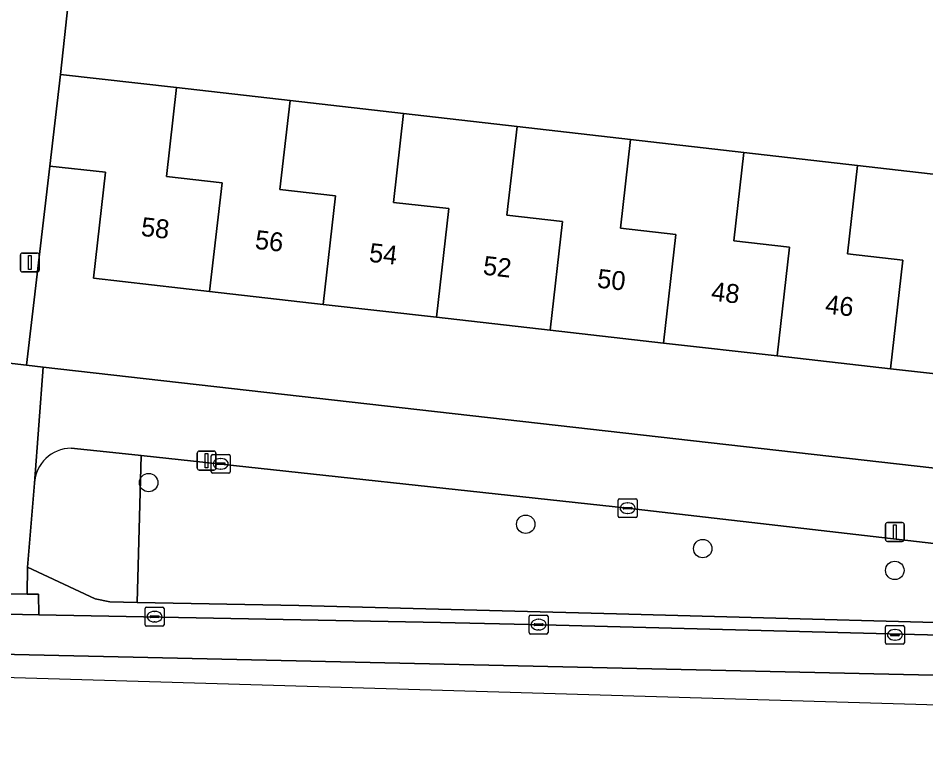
# Model space of a CAD drawing. Extents: x 162082 to 163401, y 388089 to 388636.
# Drawn here: x 162750.85 to 162798.94, y 388092.06 to 388131.14 of the extents above; entities that cross this region are included whole.
import ezdxf

# ---------------------------------------------------------------- set-up
doc = ezdxf.new("R2010")
doc.units = 0
for name, color, linetype in [('IMGEO_Boom', 7, 'Continuous'), ('IMGEO_Erf', 7, 'Continuous'), ('IMGEO_Groenvoorziening', 7, 'Continuous'), ('IMGEO_Kolk', 7, 'Continuous'), ('IMGEO_Lichtmast', 7, 'Continuous'), ('IMGEO_Pand', 7, 'Continuous'), ('IMGEO_Pand_nummerreeks', 7, 'Continuous'), ('IMGEO_Parkeervlak_gesloten', 7, 'Continuous'), ('IMGEO_Rijbaan_lokaal_gesloten', 7, 'Continuous'), ('IMGEO_Voetpad_open', 7, 'Continuous')]:
    doc.layers.add(name, color=color, linetype=linetype)

msp = doc.modelspace()

# ---------------------------------------------------------------- linework, layer by layer
at = {"layer": 'IMGEO_Boom'}
for centre in [(162757.767, 388106.537), (162777.745, 388104.33), (162787.124, 388103.04), (162797.299, 388101.885)]:
    msp.add_circle(centre, 0.489, dxfattribs=at)
at = {"layer": 'IMGEO_Erf'}
for points in [[(162817.616, 388132.026), (162813.209, 388132.465), (162813.117, 388131.452), (162774.618, 388135.355), (162754.126, 388137.65), (162753.09, 388128.162), (162759.25, 388127.458), (162765.261, 388126.772), (162771.273, 388126.085), (162777.284, 388125.399), (162783.297, 388124.712), (162789.309, 388124.025), (162795.321, 388123.339), (162801.333, 388122.652), (162807.344, 388121.965), (162813.503, 388121.262), (162816.444, 388120.926)], [(162797.073, 388112.567), (162791.061, 388113.249), (162785.049, 388113.931), (162779.036, 388114.613), (162773.023, 388115.295), (162767.011, 388115.977), (162760.999, 388116.659), (162754.84, 388117.358), (162755.477, 388122.974), (162752.539, 388123.307), (162751.303, 388112.757), (162752.175, 388112.658), (162814.697, 388105.571), (162815.061, 388108.754), (162815.261, 388110.504), (162809.099, 388111.203), (162803.086, 388111.885)]]:
    msp.add_lwpolyline(points, close=True, dxfattribs=at)
at = {"layer": 'IMGEO_Groenvoorziening'}
msp.add_lwpolyline([(162751.719, 388106.5), (162751.357, 388102.059), (162754.926, 388100.382), (162755.718, 388100.214), (162757.157, 388100.187), (162757.371, 388107.966), (162755.871, 388108.128), (162753.663, 388108.356)], dxfattribs=at)
msp.add_lwpolyline([(162765.73, 388100.028), (162782.561, 388099.591), (162807.227, 388098.913), (162807.323, 388102.396), (162783.141, 388105.183), (162757.371, 388107.966), (162757.157, 388100.187)], close=True, dxfattribs=at)
msp.add_arc((162753.669, 388106.404), 1.952, 90.1741, 177.1727, dxfattribs=at)
at = {"layer": 'IMGEO_Kolk'}
for p, q in [((162761.085, 388107.106), (162761.085, 388107.958)), ((162761.16, 388108.032), (162762.012, 388108.032)), ((162761.573, 388107.812), (162761.598, 388107.812)), ((162762.086, 388107.958), (162762.086, 388107.106)), ((162761.344, 388107.526), (162761.344, 388107.538)), ((162761.782, 388107.489), (162761.384, 388107.489)), ((162761.387, 388107.575), (162761.785, 388107.575)), ((162761.596, 388107.252), (162761.571, 388107.252)), ((162761.828, 388107.538), (162761.828, 388107.526)), ((162762.012, 388107.032), (162761.16, 388107.032)), ((162782.719, 388105.683), (162783.571, 388105.683)), ((162782.644, 388104.757), (162782.644, 388105.609)), ((162782.946, 388105.226), (162783.344, 388105.226)), ((162783.132, 388105.463), (162783.157, 388105.463)), ((162783.645, 388105.609), (162783.645, 388104.757)), ((162782.903, 388105.177), (162782.903, 388105.189)), ((162783.341, 388105.14), (162782.943, 388105.14)), ((162783.155, 388104.903), (162783.13, 388104.903)), ((162783.387, 388105.189), (162783.387, 388105.177)), ((162783.571, 388104.683), (162782.719, 388104.683)), ((162757.657, 388099.935), (162758.509, 388099.935)), ((162757.582, 388099.009), (162757.582, 388099.861)), ((162757.841, 388099.429), (162757.841, 388099.441)), ((162757.884, 388099.478), (162758.282, 388099.478)), ((162758.07, 388099.715), (162758.095, 388099.715)), ((162758.325, 388099.441), (162758.325, 388099.429)), ((162758.583, 388099.861), (162758.583, 388099.009)), ((162777.926, 388098.589), (162777.926, 388099.441)), ((162778.001, 388099.515), (162778.853, 388099.515)), ((162778.927, 388099.441), (162778.927, 388098.589)), ((162758.279, 388099.392), (162757.881, 388099.392)), ((162758.093, 388099.155), (162758.068, 388099.155)), ((162778.185, 388099.009), (162778.185, 388099.021)), ((162778.623, 388098.972), (162778.225, 388098.972)), ((162778.228, 388099.058), (162778.626, 388099.058)), ((162778.414, 388099.295), (162778.439, 388099.295)), ((162778.669, 388099.021), (162778.669, 388099.009)), ((162796.881, 388098.97), (162797.733, 388098.97)), ((162758.509, 388098.935), (162757.657, 388098.935)), ((162778.853, 388098.515), (162778.001, 388098.515)), ((162778.437, 388098.735), (162778.412, 388098.735)), ((162796.806, 388098.044), (162796.806, 388098.896)), ((162797.065, 388098.464), (162797.065, 388098.476)), ((162797.108, 388098.513), (162797.506, 388098.513)), ((162797.294, 388098.75), (162797.319, 388098.75)), ((162797.549, 388098.476), (162797.549, 388098.464)), ((162797.807, 388098.896), (162797.807, 388098.044)), ((162797.503, 388098.427), (162797.105, 388098.427)), ((162797.317, 388098.19), (162797.292, 388098.19)), ((162797.733, 388097.97), (162796.881, 388097.97))]:
    msp.add_line(p, q, dxfattribs=at)
for points in [[(162761.085, 388107.106), (162761.085, 388107.958)], [(162761.16, 388108.032), (162762.012, 388108.032)], [(162762.086, 388107.958), (162762.086, 388107.106)], [(162762.012, 388107.032), (162761.16, 388107.032)], [(162782.719, 388105.683), (162783.571, 388105.683)], [(162782.644, 388104.757), (162782.644, 388105.609)], [(162783.645, 388105.609), (162783.645, 388104.757)], [(162783.571, 388104.683), (162782.719, 388104.683)], [(162757.657, 388099.935), (162758.509, 388099.935)], [(162757.582, 388099.009), (162757.582, 388099.861)], [(162758.583, 388099.861), (162758.583, 388099.009)], [(162777.926, 388098.589), (162777.926, 388099.441)], [(162778.001, 388099.515), (162778.853, 388099.515)], [(162778.927, 388099.441), (162778.927, 388098.589)], [(162796.881, 388098.97), (162797.733, 388098.97)], [(162758.509, 388098.935), (162757.657, 388098.935)], [(162778.853, 388098.515), (162778.001, 388098.515)], [(162796.806, 388098.044), (162796.806, 388098.896)], [(162797.807, 388098.896), (162797.807, 388098.044)], [(162797.733, 388097.97), (162796.881, 388097.97)]]:
    msp.add_lwpolyline(points, dxfattribs=at)
for centre, radius, start, end in [((162761.162, 388107.956), 0.0765, 91.552, 178.448), ((162761.162, 388107.956), 0.0765, 91.552, 178.448), ((162762.01, 388107.956), 0.0765, 1.552, 88.448), ((162762.01, 388107.956), 0.0765, 1.552, 88.448), ((162761.384, 388107.535), 0.0403, 85.8775, 175.7526), ((162761.381, 388107.525), 0.0366, 178.938, 274.7102), ((162761.785, 388107.532), 0.043, 264.8664, 352.4533), ((162761.789, 388107.537), 0.0386, 1.7309, 96.639), ((162761.162, 388107.108), 0.0765, 181.552, 268.448), ((162761.162, 388107.108), 0.0765, 181.552, 268.448), ((162762.01, 388107.108), 0.0765, 271.552, 358.448), ((162762.01, 388107.108), 0.0765, 271.552, 358.448), ((162782.721, 388105.607), 0.0765, 91.552, 178.448), ((162782.721, 388105.607), 0.0765, 91.552, 178.448), ((162783.569, 388105.607), 0.0765, 1.552, 88.448), ((162783.569, 388105.607), 0.0765, 1.552, 88.448), ((162782.943, 388105.186), 0.0403, 85.8775, 175.7526), ((162783.348, 388105.188), 0.0386, 1.7309, 96.639), ((162782.721, 388104.759), 0.0765, 181.552, 268.448), ((162782.721, 388104.759), 0.0765, 181.552, 268.448), ((162782.94, 388105.176), 0.0366, 178.938, 274.7102), ((162783.344, 388105.183), 0.043, 264.8664, 352.4533), ((162783.569, 388104.759), 0.0765, 271.552, 358.448), ((162783.569, 388104.759), 0.0765, 271.552, 358.448), ((162757.659, 388099.859), 0.0765, 91.552, 178.448), ((162757.659, 388099.859), 0.0765, 91.552, 178.448), ((162758.507, 388099.859), 0.0765, 1.552, 88.448), ((162758.507, 388099.859), 0.0765, 1.552, 88.448), ((162757.881, 388099.438), 0.0403, 85.8775, 175.7526), ((162757.878, 388099.428), 0.0366, 178.938, 274.7102), ((162758.282, 388099.435), 0.043, 264.8664, 352.4533), ((162758.286, 388099.44), 0.0386, 1.7309, 96.639), ((162778.003, 388099.439), 0.0765, 91.552, 178.448), ((162778.003, 388099.439), 0.0765, 91.552, 178.448), ((162778.851, 388099.439), 0.0765, 1.552, 88.448), ((162778.851, 388099.439), 0.0765, 1.552, 88.448), ((162757.659, 388099.011), 0.0765, 181.552, 268.448), ((162757.659, 388099.011), 0.0765, 181.552, 268.448), ((162758.507, 388099.011), 0.0765, 271.552, 358.448), ((162758.507, 388099.011), 0.0765, 271.552, 358.448), ((162778.225, 388099.018), 0.0403, 85.8775, 175.7526), ((162778.222, 388099.008), 0.0366, 178.938, 274.7102), ((162778.626, 388099.015), 0.043, 264.8664, 352.4533), ((162778.63, 388099.02), 0.0386, 1.7309, 96.639), ((162796.883, 388098.894), 0.0765, 91.552, 178.448), ((162796.883, 388098.894), 0.0765, 91.552, 178.448), ((162797.731, 388098.894), 0.0765, 1.552, 88.448), ((162797.731, 388098.894), 0.0765, 1.552, 88.448), ((162778.003, 388098.591), 0.0765, 181.552, 268.448), ((162778.003, 388098.591), 0.0765, 181.552, 268.448), ((162778.851, 388098.591), 0.0765, 271.552, 358.448), ((162778.851, 388098.591), 0.0765, 271.552, 358.448), ((162797.105, 388098.473), 0.0403, 85.8775, 175.7526), ((162797.102, 388098.463), 0.0366, 178.938, 274.7102), ((162797.506, 388098.47), 0.043, 264.8664, 352.4533), ((162797.51, 388098.475), 0.0386, 1.7309, 96.639), ((162796.883, 388098.046), 0.0765, 181.552, 268.448), ((162796.883, 388098.046), 0.0765, 181.552, 268.448), ((162797.731, 388098.046), 0.0765, 271.552, 358.448), ((162797.731, 388098.046), 0.0765, 271.552, 358.448)]:
    msp.add_arc(centre, radius, start, end, dxfattribs=at)
for centre, major_axis, ratio, start_param, end_param in [((162761.572, 388107.532), (-0.387, 0.002), 0.722429, 4.712389, 7.853982), ((162761.597, 388107.532), (-0.39, 0.002), 0.717154, 1.570796, 4.712389), ((162783.131, 388105.183), (-0.387, 0.002), 0.722429, 4.712389, 7.853982), ((162783.156, 388105.183), (-0.39, 0.002), 0.717154, 1.570796, 4.712389), ((162758.069, 388099.435), (-0.387, 0.002), 0.722429, 4.712389, 7.853982), ((162758.094, 388099.435), (-0.39, 0.002), 0.717154, 1.570796, 4.712389), ((162778.413, 388099.015), (-0.387, 0.002), 0.722429, 4.712389, 7.853982), ((162778.438, 388099.015), (-0.39, 0.002), 0.717154, 1.570796, 4.712389), ((162797.293, 388098.47), (-0.387, 0.002), 0.722429, 4.712389, 7.853982), ((162797.318, 388098.47), (-0.39, 0.002), 0.717154, 1.570796, 4.712389)]:
    msp.add_ellipse(centre, major_axis=major_axis, ratio=ratio, start_param=start_param, end_param=end_param, dxfattribs=at)
at = {"layer": 'IMGEO_Lichtmast'}
for p, q in [((162751.077, 388118.698), (162751.867, 388118.698)), ((162751.867, 388118.698), (162751.077, 388118.698)), ((162750.977, 388117.798), (162750.977, 388118.598)), ((162750.977, 388118.598), (162750.977, 388117.798)), ((162751.967, 388118.598), (162751.967, 388117.798)), ((162751.967, 388117.798), (162751.967, 388118.598)), ((162751.867, 388117.698), (162751.077, 388117.698)), ((162751.077, 388117.698), (162751.867, 388117.698)), ((162760.339, 388107.302), (162760.339, 388108.102)), ((162760.339, 388108.102), (162760.339, 388107.302)), ((162760.439, 388108.202), (162761.229, 388108.202)), ((162761.229, 388108.202), (162760.439, 388108.202)), ((162761.329, 388108.102), (162761.329, 388107.302)), ((162761.329, 388107.302), (162761.329, 388108.102)), ((162761.229, 388107.202), (162760.439, 388107.202)), ((162760.439, 388107.202), (162761.229, 388107.202)), ((162796.805, 388103.52), (162796.805, 388104.32)), ((162796.805, 388104.32), (162796.805, 388103.52)), ((162796.905, 388104.42), (162797.695, 388104.42)), ((162797.695, 388104.42), (162796.905, 388104.42)), ((162797.795, 388104.32), (162797.795, 388103.52)), ((162797.795, 388103.52), (162797.795, 388104.32)), ((162797.695, 388103.42), (162796.905, 388103.42)), ((162796.905, 388103.42), (162797.695, 388103.42))]:
    msp.add_line(p, q, dxfattribs=at)
for points in [[(162751.397, 388118.573), (162751.547, 388118.573), (162751.547, 388117.823), (162751.397, 388117.823), (162751.397, 388118.573)], [(162760.759, 388108.077), (162760.909, 388108.077), (162760.909, 388107.327), (162760.759, 388107.327), (162760.759, 388108.077)], [(162797.225, 388104.295), (162797.375, 388104.295), (162797.375, 388103.545), (162797.225, 388103.545), (162797.225, 388104.295)]]:
    msp.add_lwpolyline(points, dxfattribs=at)
for centre, start, end in [((162751.077, 388118.598), 90, 180), ((162751.077, 388118.598), 90, 180), ((162751.867, 388118.598), 0, 90), ((162751.867, 388118.598), 360, 90), ((162751.077, 388117.798), 180, 270), ((162751.077, 388117.798), 180, 270), ((162751.867, 388117.798), 270, 0), ((162751.867, 388117.798), 270, 0), ((162760.439, 388108.102), 90, 180), ((162760.439, 388108.102), 90, 180), ((162761.229, 388108.102), 0, 90), ((162761.229, 388108.102), 360, 90), ((162760.439, 388107.302), 180, 270), ((162760.439, 388107.302), 180, 270), ((162761.229, 388107.302), 270, 0), ((162761.229, 388107.302), 270, 0), ((162796.905, 388104.32), 90, 180), ((162796.905, 388104.32), 90, 180), ((162797.695, 388104.32), 0, 90), ((162797.695, 388104.32), 360, 90), ((162796.905, 388103.52), 180, 270), ((162796.905, 388103.52), 180, 270), ((162797.695, 388103.52), 270, 0), ((162797.695, 388103.52), 270, 0)]:
    msp.add_arc(centre, 0.1, start, end, dxfattribs=at)
at = {"layer": 'IMGEO_Pand'}
for points in [[(162760.999, 388116.659), (162761.654, 388122.414), (162758.714, 388122.747), (162759.25, 388127.458), (162753.09, 388128.162), (162752.539, 388123.307), (162755.477, 388122.974), (162754.84, 388117.358)], [(162765.261, 388126.772), (162759.25, 388127.458), (162758.714, 388122.747), (162761.654, 388122.414), (162760.999, 388116.659), (162767.011, 388115.977), (162767.666, 388121.732), (162764.726, 388122.065)], [(162765.261, 388126.772), (162764.726, 388122.065), (162767.666, 388121.732), (162767.011, 388115.977), (162773.023, 388115.295), (162773.678, 388121.049), (162770.738, 388121.383), (162771.273, 388126.085)], [(162777.284, 388125.399), (162771.273, 388126.085), (162770.738, 388121.383), (162773.678, 388121.049), (162773.023, 388115.295), (162779.036, 388114.613), (162779.691, 388120.367), (162776.75, 388120.701)], [(162777.284, 388125.399), (162776.75, 388120.701), (162779.691, 388120.367), (162779.036, 388114.613), (162785.049, 388113.931), (162785.703, 388119.685), (162782.763, 388120.019), (162783.297, 388124.712)], [(162785.049, 388113.931), (162791.061, 388113.249), (162791.715, 388119.003), (162788.776, 388119.336), (162789.309, 388124.025), (162783.297, 388124.712), (162782.763, 388120.019), (162785.703, 388119.685)], [(162791.061, 388113.249), (162797.073, 388112.567), (162797.728, 388118.321), (162794.788, 388118.654), (162795.321, 388123.339), (162789.309, 388124.025), (162788.776, 388119.336), (162791.715, 388119.003)], [(162801.333, 388122.652), (162795.321, 388123.339), (162794.788, 388118.654), (162797.728, 388118.321), (162797.073, 388112.567), (162803.086, 388111.885), (162803.741, 388117.639), (162800.8, 388117.972)]]:
    msp.add_lwpolyline(points, close=True, dxfattribs=at)
at = {"layer": 'IMGEO_Parkeervlak_gesloten'}
for points in [[(162818.175, 388097.964), (162813.273, 388098.093), (162778.686, 388099.006), (162773.226, 388099.133), (162751.947, 388099.538), (162744.969, 388099.668), (162734.332, 388099.937), (162723.767, 388100.411), (162721.042, 388100.533), (162687.414, 388104.072), (162680.434, 388104.818), (162676.729, 388105.31), (162660.98, 388106.977)], [(162658.176, 388105.434), (162658.296, 388105.083), (162718.662, 388098.447), (162728.664, 388097.932), (162862.144, 388094.92), (162891.178, 388094.283), (162891.207, 388096.101), (162889.955, 388096.125), (162887.136, 388096.178), (162870.728, 388096.577), (162866.082, 388096.7), (162818.175, 388097.964)]]:
    msp.add_lwpolyline(points, dxfattribs=at)
at = {"layer": 'IMGEO_Rijbaan_lokaal_gesloten'}
msp.add_lwpolyline([(162614.551, 388108.282), (162640.082, 388105.43), (162649.021, 388104.431), (162698.466, 388098.908), (162712.432, 388097.348), (162866.457, 388092.792), (162891.143, 388092.062), (162891.178, 388094.283), (162862.144, 388094.92), (162728.664, 388097.932), (162718.662, 388098.447), (162658.296, 388105.083), (162658.176, 388105.434)], dxfattribs=at)
at = {"layer": 'IMGEO_Voetpad_open'}
for points in [[(162752.539, 388123.307), (162753.09, 388128.162), (162754.126, 388137.65), (162751.105, 388137.978), (162750.849, 388135.576), (162750.73, 388134.453), (162750.72, 388134.36), (162749.751, 388125.412), (162749.254, 388120.826), (162748.606, 388115.036), (162748.395, 388113.098), (162751.303, 388112.757)], [(162751.936, 388100.619), (162751.331, 388100.63), (162745.028, 388100.744), (162744.969, 388099.668), (162751.947, 388099.538)]]:
    msp.add_lwpolyline(points, close=True, dxfattribs=at)
for points in [[(162752.175, 388112.658), (162751.303, 388112.757), (162748.395, 388113.098), (162748.067, 388110.086), (162684.724, 388117.321), (162683.276, 388117.486), (162682.179, 388107.971), (162670.857, 388109.168), (162668.681, 388109.418), (162662.214, 388110.161), (162657.492, 388110.617), (162652.357, 388111.094)], [(162660.98, 388106.977), (162676.729, 388105.31), (162680.434, 388104.818), (162680.522, 388105.889), (162687.541, 388105.077), (162687.414, 388104.072), (162721.042, 388100.533), (162723.767, 388100.411), (162734.332, 388099.937), (162744.969, 388099.668), (162745.028, 388100.744), (162751.331, 388100.63), (162751.357, 388102.059), (162751.719, 388106.5), (162751.712, 388106.508), (162752.175, 388112.658)], [(162818.784, 388108.339), (162818.122, 388108.413), (162815.061, 388108.754), (162814.697, 388105.571), (162752.175, 388112.658), (162751.712, 388106.508), (162751.719, 388106.5)], [(162812.578, 388099.868), (162812.124, 388099.838), (162809.372, 388098.854), (162807.227, 388098.913), (162782.561, 388099.591), (162765.73, 388100.028), (162757.157, 388100.187), (162755.718, 388100.214), (162754.926, 388100.382), (162751.357, 388102.059), (162751.331, 388100.63), (162751.936, 388100.619), (162751.947, 388099.538), (162773.226, 388099.133), (162778.686, 388099.006), (162813.273, 388098.093), (162813.286, 388098.552), (162817.975, 388098.435), (162818.009, 388100.549), (162818.025, 388100.623), (162818.194, 388102.188), (162818.784, 388108.339)], [(162753.663, 388108.356), (162755.871, 388108.128), (162757.371, 388107.966), (162783.141, 388105.183), (162807.323, 388102.396), (162812.624, 388101.785)]]:
    msp.add_lwpolyline(points, dxfattribs=at)
msp.add_arc((162753.669, 388106.404), 1.952, 90.1741, 177.1727, dxfattribs=at)

# ---------------------------------------------------------------- texts
at = {"layer": 'IMGEO_Pand_nummerreeks'}
for s, p in [('58', (162757.327, 388119.612)), ('56', (162763.366, 388118.926)), ('54', (162769.408, 388118.241)), ('52', (162775.447, 388117.557)), ('50', (162781.495, 388116.87)), ('48', (162787.537, 388116.185)), ('46', (162793.577, 388115.499))]:
    msp.add_text(s, height=1, rotation=353.5282, dxfattribs=at).set_placement(p)

doc.saveas('drawing.dxf')
